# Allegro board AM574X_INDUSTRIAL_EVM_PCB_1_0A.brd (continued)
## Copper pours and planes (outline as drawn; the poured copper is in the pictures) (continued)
VDD_DSPEVE on L3_SIG1: 104.72,86.18 106.73,86.18 107.01,85.9 107.01,83.79 107.06,83.74 107.67,83.74 107.77,83.64 107.77,83.29 107.34,82.85 104.8,82.85 104.5,83.16 104.5,85.95
VDD_DSPEVE on L4_SIG2: 115.06,104.09 116.59,102.57 123.95,102.57 134.87,113.49 134.87,120.86 136.4,122.38 136.4,123.78 125.17,135.01 117.86,135.01 117.42,134.57 117.35,134.57 116.84,134.07 116.84,107.27 115.06,105.49
VDD_DSPEVE on L8_GND3: 112.39,106 111.63,105.24 111.63,93.43 107.19,88.98 107.19,87.84 105.92,86.57 105.28,86.57 104.77,86.06 104.77,83.39 105.03,83.14 107.44,83.14 107.7,83.39 107.7,83.77 109.09,85.17 121.03,85.17 123.95,88.09 123.95,105.49 123.44,106
VDD_DSPEVE on L10_SIG4: 113.54,87.08 114.43,87.08 115.19,86.31 115.19,84.92 115.06,84.79 113.54,84.79 113.03,85.3 113.03,86.57
VDD_DSPEVE on L10_SIG4: 115.34,103.69 115.06,103.97 115.06,104.98 115.95,105.87 117.98,105.87 118.69,105.16 118.69,104.12 118.26,103.69
VDD_DSPEVE on L10_SIG4: 115.19,98.13 115.19,98.89 115.57,99.27 117.37,99.27 117.47,99.17 117.47,98 117.07,97.59 115.72,97.59
VDD_DSPEVE on L10_SIG4: 104.65,86.14 106.86,86.14 106.98,86.01 106.98,83.49 106.5,83.01 105.03,83.01 104.42,83.62 104.42,85.91
VDD_GPU on TOP: 133.86,113.62 136.53,113.62 136.91,113.24 136.91,110.83 136.65,110.57 133.86,110.57 133.48,110.95 133.48,113.24
VDD_GPU on BOTTOM: 86.49,89.11 92.2,89.11 92.33,88.98 92.33,87.97 91.82,87.46 90.42,87.46 90.3,87.33 90.3,87.2 90.17,87.08 86.49,87.08 86.23,87.33 86.23,88.85
VDD_GPU on BOTTOM: 96.93,86.62 99.34,86.62 99.56,86.4 99.56,85.56 100.05,85.07 100.05,83.92 99.95,83.82 98.96,83.82 98.27,84.51 97.23,84.51 97.16,84.58 97.16,85.78 96.82,86.11 96.82,86.52
VDD_GPU on BOTTOM: 133.48,113.37 136.78,113.37 137.03,113.11 137.03,110.83 136.78,110.57 133.99,110.57 133.35,111.21 133.35,113.24
VDD_GPU on L3_SIG1: 97.69,86.21 98.73,86.21 100.03,84.91 100.03,83.97 99.9,83.85 98.65,83.85 98.4,83.59 98.4,83.36 99.21,82.55 99.21,82.17 99.11,82.07 97.94,82.07 97.54,82.47 97.54,86.06
VDD_GPU on L9_SIG3: 109.6,125.48 138.51,125.48 140.02,123.97 140.02,120.92 138.81,119.72 138.81,112.86 131.44,105.49 126.49,105.49 120.78,99.78 107.95,99.78 104.01,95.84 104.01,87.08 98.93,82 93.09,82 91.99,83.1 94.92,83.1 96.04,84.22 96.04,86.52 94.92,87.64 93.66,87.64 92.37,86.34 90.44,86.34 88.97,87.81 88.97,90.05 87.7,91.33 86.95,91.33 86.68,91.6 86.68,102.57 86.99,102.87
VDD_GPU on L10_SIG4: 86.23,88.85 86.36,88.98 92.2,88.98 92.46,88.73 92.46,87.84 91.95,87.33 90.04,87.33 89.79,87.08 86.36,87.08 86.23,87.2
VDD_GPU on L10_SIG4: 97.69,86.21 98.73,86.21 99.77,85.17 99.77,84.58 98.78,84.58 98.17,85.19 97.54,85.19 97.54,86.06
VDD_IVA on TOP: 143.26,113.62 146.05,113.62 146.43,113.24 146.43,110.95 146.18,110.7 143.38,110.7 143,111.08 143,113.37
VDD_IVA on BOTTOM: 89.89,78.08 90.17,78.36 92.84,78.36 93.22,77.98 98.34,77.98 99.11,78.74 99.82,78.74 100.03,78.54 100.03,77.07 99.69,76.74 93.47,76.74 91.28,74.55 90.04,74.55 89.89,74.7
VDD_IVA on L3_SIG1: 98.58,78.59 99.85,78.59 100.1,78.33 100.1,77.29 99.52,77.29 99.31,77.5 98.6,77.5 98.4,77.7 98.4,78.41
VDD_IVA on L9_SIG3: 98.78,76.33 98.3,76.81 98.3,80.77 98.71,81.18 99.11,81.18 104.77,86.84 104.77,95.2 108.97,99.4 120.9,99.4 126.62,105.11 131.95,105.11 139.52,112.68 139.52,119.79 140.21,120.48 140.21,122.64 140.61,123.04 146.94,123.04 147.57,122.41 147.57,111.51 140.42,104.35 140.42,103.8 117.42,80.8 108.46,80.8 103.99,76.33
VDD_IVA on L10_SIG4: 98.58,78.59 99.85,78.59 100.1,78.33 100.1,76.96 99.14,76.96 98.4,77.7 98.4,78.41
VDD_MIPI on TOP: 154.18,99.14 154.43,98.89 154.43,97.36 154.31,97.24 153.04,97.24 152.91,97.36 152.91,97.74 152.4,98.25 148.34,98.25 147.96,98.63 147.96,98.89 148.21,99.14
VDD_MPU on TOP: 108.84,133.81 109.35,134.32 112.27,134.32 112.27,131.02 114.81,128.48 118.75,128.48 119.76,127.46 119.76,122.51 118.87,121.62 114.55,121.62 108.84,127.34
VDD_MPU on TOP: 144.78,130.89 144.78,131.78 145.03,132.03 145.03,134.45 145.29,134.7 146.69,134.7 146.94,134.45 146.94,132.67 145.03,130.76 144.91,130.76
VDD_MPU on TOP: 102.95,79.83 104.06,79.83 104.34,80.11 105.82,80.11 106.5,79.43 106.5,77.42 105.23,77.42 104.44,78.21 102.95,78.21
VDD_MPU on BOTTOM: 101.17,79.71 101.42,79.96 102.49,79.96 102.97,79.48 102.97,79.05 102.77,78.85 101.5,78.85 101.17,79.18
VDD_MPU on BOTTOM: 105.97,80.17 106.96,80.17 107.19,79.94 107.19,79.58 106.91,79.3 106.88,79.3 106.88,78.47 108.89,78.47 109.14,78.21 109.14,76.74 108.99,76.59 108.1,76.59 107.72,76.97 106.86,76.97 106.81,76.92 106.76,76.92 106.07,77.6 104.42,77.6 104.29,77.73 104.29,80.7 104.7,81.11 105.66,81.11 105.79,80.98 105.79,80.35
VDD_MPU on BOTTOM: 95.63,95.97 99.31,95.97 99.57,95.71 99.57,94.49 99.31,94.23 95.59,94.23 95.38,94.44 95.38,95.71
VDD_MPU on BOTTOM: 115.64,80.42 117.15,80.42 117.3,80.27 117.3,78.94 117.09,78.74 115.91,78.74 115.44,79.2 115.44,80.22
VDD_MPU on L3_SIG1: 102.84,77.88 104.85,77.88 105.54,77.19 106.2,77.19 106.98,77.98 106.98,79.27 106.78,79.48 106.55,79.48 106.1,79.93 106.1,80.19 104.72,80.19 104.72,79.45 104.39,79.12 103.58,79.12 103.3,79.4 102.87,79.4 102.69,79.22 102.69,78.03
VDD_MPU on L6_PWR1: 95.63,118.19 106.81,129.37 106.81,129.24 107.7,130.13 116.97,130.13 126.87,140.04 144.91,140.04 147.19,137.75 147.19,131.91 146.56,131.27 144.65,131.27 143.13,132.8 141.22,132.8 140.59,132.16 138.68,132.16 137.67,133.18 133.48,133.18 128.02,127.72 128.02,116.03 121.67,109.68 121.67,105.36 119.63,103.33 119.63,77.68 119.04,77.09 100.79,77.09 100.61,77.27 100.61,81.76 101.42,82.58 101.42,88.4 95.63,94.19
VDD_MPU on L10_SIG4: 102.49,80.09 103.35,79.23 104.32,79.23 104.57,79.48 104.57,80.6 104.55,80.62 104.55,80.75 104.83,81.03 105.77,81.03 106.07,80.73 106.07,79.84 106.88,79.02 106.88,78.08 106.73,77.93 100.86,77.93 100.84,77.91 100.71,78.03 100.71,78.41 100.79,78.49 101.27,78.49 101.47,78.69 101.47,79.96 101.6,80.09
VDD_MPU on L10_SIG4: 95.89,94.06 95.89,95.59 96.52,96.22 97.41,96.22 97.79,95.84 97.79,93.43 97.54,93.17 96.77,93.17
VDD_RTC on TOP: 138.59,131.73 138.48,131.62 138.48,131.37 138.21,131.1 138.05,131.1 138.05,131.25 137.94,131.36 137.94,133.32 138.18,133.56 138.43,133.56 138.59,133.4
VDD_RTC on BOTTOM: 79.88,86.11 80.52,86.11 80.77,86.36 80.77,86.74 81.03,87 81.03,88.01 80.9,88.14 80.26,88.14 79.76,87.63 79.76,86.23
VDD_RTC on L9_SIG3: 105.11,134.19 138.3,134.19 139.32,133.18 139.32,127.21 138.35,126.24 109.09,126.24 85.85,103 85.85,91.49 85.22,90.85 85.22,89.92 81.79,86.49 81.79,85.09 81.53,84.84 80.26,84.84 78.11,87 78.11,107.19
VDD_RTC on L10_SIG4: 80.26,88.01 81.03,88.01 81.28,87.76 81.28,87.38 81.03,87.12 81.03,86.23 80.64,85.85 79.88,85.85 79.5,86.23 79.5,87.25
VDDR2_VREF on BOTTOM: 139.7,70.82 141.22,70.82 141.48,70.57 141.48,67.14 140.59,66.25 140.21,66.25 139.45,67.01 139.45,70.57
VDDR2_VREF on BOTTOM: 139.7,55.58 141.22,55.58 141.48,55.33 141.48,51.9 140.59,51.01 140.21,51.01 139.45,51.77 139.45,55.33
VDDR2_VREF on BOTTOM: 162.08,59.87 162.08,58.32 160.96,58.32 160.96,59.21 159,61.17 159,63.07 155.19,66.88 155.19,70.19 151.38,74 141.86,74 140.34,72.47 138.56,72.47 138.18,72.85 138.18,74.63 139.57,76.03 152.65,76.03 157.35,71.33 157.35,67.67 161.42,63.61 161.42,60.53
VDDR2_VREF on L7_PWR2: 141.35,45.42 138.68,48.09 138.68,56.98 137.67,57.99 117.98,57.99 108.84,67.14 108.84,70.19 107.06,71.96 104.77,71.96 103.63,73.11 103.63,74.76 104.01,75.14 109.35,75.14 111.63,72.85 111.63,68.33 117.73,62.23 129.71,62.23 133.73,66.25 133.73,71.58 136.95,74.8 140.04,74.8 143.89,70.95 143.89,62.86 144.4,62.36 144.4,60.83 143.89,60.32 143.89,46.06 143.26,45.42
VDDR2_VTT on TOP: 142.75,71.07 150.41,71.07 151.13,70.36 151.13,56.98 151.38,56.72 152.15,56.72 152.91,57.49 158.12,57.49 158.24,57.61 158.24,58.88 158.12,59.01 153.54,59.01 152.91,59.64 152.91,70.99 151.05,72.85 142.75,72.85 142.49,72.6 142.49,71.33
VDDR2_VTT on BOTTOM: 151.13,70.31 150.37,71.07 141.86,71.07 141.61,71.33 141.61,72.6 141.86,72.85 151,72.85 152.91,70.95 152.91,60.66 154.46,59.11 156.01,59.11 156.21,58.91 156.21,58.42 156.44,58.2 157,58.2 157.15,58.04 157.15,57.84 157.05,57.74 157.05,57.66 156.97,57.59 156.97,57.49 151.38,57.49 151.13,57.74
VDDR_VREF on TOP: 78.61,33.78 81.03,33.78 82.04,32.77 82.93,32.77 83.06,32.89 83.31,32.89 83.44,32.77 83.44,32.51 82.8,31.88 78.49,31.88 78.11,32.26 78.11,33.27
VDDR_VREF on TOP: 93.85,33.78 96.27,33.78 97.28,32.77 98.17,32.77 98.3,32.89 98.55,32.89 98.68,32.77 98.68,32.51 98.04,31.88 93.73,31.88 93.34,32.26 93.34,33.27
VDDR_VREF on TOP: 105.44,12.55 106.98,12.55 106.98,13.67 106.1,13.67 104.14,15.62 98.76,15.62 92.79,21.59 91.19,21.59 90.68,21.08 90.68,20.19 97.66,13.21 104.77,13.21
VDDR_VREF on TOP: 109.09,33.78 111.51,33.78 112.52,32.77 113.41,32.77 113.54,32.89 113.79,32.89 113.92,32.77 113.92,32.51 113.28,31.88 108.97,31.88 108.58,32.26 108.58,33.27
VDDR_VREF on L7_PWR2: 92.46,18.83 90.55,20.74 90.55,26.88 88.65,28.78 83.44,28.78 82.55,29.67 82.55,33.61 83.19,34.24 86.23,34.24 95.76,43.77 95.76,65.16 96.52,65.92 96.52,78.19 96.77,78.44 99.82,78.44 100.03,78.24 100.03,77.42 102.74,74.71 102.74,38.94 103.25,38.44 120.27,38.44 123.19,35.51 123.19,27.72 122.3,26.83 97.54,26.83 96.01,25.31 96.01,19.85 95,18.83
VDDR_VTT on TOP: 107.31,17.27 107.06,17.53 107.06,17.78 106.3,18.54 106.3,27.81 106.55,28.07 108.46,28.07 108.71,27.81 108.71,25.4 109.6,24.51 110.62,24.51 111.89,23.24 111.89,22.61 112.9,21.59 120.78,21.59 121.5,20.87 124.5,20.87 125.13,21.5 125.13,24.98 124.21,25.91 124.21,27.81 124.46,28.07 125.86,28.07 126.36,28.58 126.36,30.48 125.86,30.99 124.84,30.99 124.21,31.62 124.21,32.13 124.46,32.38 127.38,32.38 129.03,30.73 129.03,26.16 128.14,25.27 128.14,20.07 126.11,18.03 118.39,18.03 115.85,20.57 111.51,20.57 109.98,22.1 108.33,22.1 107.82,21.59 107.82,17.53 107.57,17.27
VDDR_VTT on BOTTOM: 107.31,23.62 108.46,22.48 110.62,22.48 111.38,21.72 111.38,19.3 111.76,18.92 127.13,18.92 128.35,20.14 128.35,29.69 128.07,29.97 124.41,29.97 124.21,29.77 124.21,22.48 123.32,21.59 114.05,21.59 113.54,22.1 113.54,22.61 108.71,27.43 108.71,28.19 108.58,28.32 108.58,30.61 108.46,30.73 107.57,30.73 107.31,30.48
VDDS_DDR on TOP: 108.71,17.06 109.09,17.44 109.09,17.95 109.73,18.59 109.73,20.11 109.98,20.37 109.98,21.46 109.73,21.72 108.46,21.72 108.2,21.46 108.2,17.06
VDDS_DDR on TOP: 141.48,53.04 141.86,53.04 142.11,52.79 142.11,51.52 142.37,51.26 142.37,50.37 141.86,49.87 141.61,49.87 141.35,50.12 141.35,51.14 141.22,51.26 141.22,52.79
VDDS_DDR on TOP: 61.09,75.01 64.01,75.01 64.14,74.88 64.14,72.6 63.63,72.09 60.96,72.09 60.58,72.47 60.58,74.5
VDDS_DDR on TOP: 65.15,56.98 65.15,54.06 65.02,53.93 62.74,53.93 62.23,54.44 62.23,57.1 62.61,57.49 64.64,57.49
VDDS_DDR on TOP: 156.08,57.1 156.21,56.98 156.21,55.71 156.08,55.58 153.16,55.58 152.91,55.83 152.91,56.85 153.16,57.1
VDDS_DDR on TOP: 136.14,63.33 136.65,63.33 137.41,64.09 137.41,65.49 137.16,65.74 136.65,65.74 135.89,64.98 135.89,63.58
VDDS_DDR on TOP: 151.64,116.67 148.46,116.67 148.21,116.92 148.21,118.32 145.61,120.92 145.61,122.19 144.91,122.89 144.91,123.02 145.16,123.27 145.54,123.27 145.8,123.02 146.94,123.02 148.72,121.24 150.5,121.24 150.88,120.86 150.88,119.46 151.89,118.45 151.89,116.92
VDDS_DDR on TOP: 135,48.21 136.4,48.21 136.65,48.47 136.65,49.48 137.16,49.99 137.16,50.25 136.78,50.63 135,50.63 134.75,50.37 134.75,48.47
VDDS_DDR on TOP: 139.19,50.37 140.21,50.37 140.56,50.02 140.56,48.57 140.08,48.09 139.19,48.09 138.94,48.34 138.94,50.12
VDDS_DDR on BOTTOM: 86.74,33.43 87.1,33.78 87.38,33.78 87.63,33.53 87.63,32.26 87.25,31.88 84.33,31.88 83.69,32.51 83.69,33.3 83.82,33.43
VDDS_DDR on BOTTOM: 83.95,36.32 85.85,36.32 86.11,36.07 86.11,35.69 85.85,35.43 83.95,35.43 83.69,35.69 83.69,36.07
VDDS_DDR on BOTTOM: 157.56,56.6 157.18,56.22 156.67,56.22 156.04,55.58 153.33,55.58 153.1,55.81 153.1,56.91 153.29,57.1 157.56,57.1
VDDS_DDR on BOTTOM: 109.86,18.54 110.11,18.8 110.11,21.46 109.73,21.84 108.58,21.84 108.2,21.46 108.2,18.67 108.33,18.54
VDDS_DDR on L6_PWR1: 151.26,119.21 144.4,119.21 141.99,116.79 133.22,116.79 132.33,115.91 132.33,114.76 126.24,108.67 126.24,105.49 125.09,104.35 121.41,104.35 120.27,103.21 120.27,77.35 119.93,77 119.93,48.63 113.66,42.37 67.18,42.37 65.15,44.4 65.15,73.84 63.91,75.09 51,75.09 49.78,73.87 49.78,26.37 51.64,24.52 65.46,24.52 71.58,18.39 82.55,18.39 84.86,16.08 97.66,16.08 99.95,18.37 111.76,18.37 112.78,17.35 113.41,17.35 114.43,18.37 164.21,18.37 168.4,22.56 168.4,66.25 163.96,70.69 156.34,70.69 152.65,74.38 152.65,87.39 152.02,88.03 143.07,88.03 140.59,90.51 140.59,101.94 152.02,113.37 152.02,118.45
AM572X_USB1_DRVVBUS on L9_SIG3: 93.7,87.33 94.74,87.33 95.76,86.31 95.76,84.27 94.82,83.33 91.56,83.33 86.5,88.39 86.5,88.4 85.72,89.18 85.72,90.63 85.98,90.89 87.46,90.89 88.55,89.8 88.55,87.97 90.48,86.03 92.41,86.03 92.41,86.04
BKLT_L on TOP: 70.86,144.25 70.36,144.75 70.36,146.41 70.74,146.79 80.13,146.79 80.64,146.28 80.64,144.63 80.26,144.25
BKLT_L on BOTTOM: 73.13,146.61 73.13,145.6 72.24,145.6 71.48,144.84 70.59,144.84 70.36,145.07 70.36,146.38 70.59,146.61
BKLT_SW on TOP: 70.74,140.94 70.36,141.33 70.36,143.48 70.74,143.87 80.26,143.87 80.64,143.48 80.64,141.58 80.01,140.94
BKLT_SW on BOTTOM: 73.15,143.57 73.15,142.7 72.27,142.7 71.86,142.3 70.34,142.3 70.09,142.55 70.09,143.31 70.34,143.57
ETH1_LDO_O on TOP: 64.64,111.08 65.53,111.08 65.79,110.83 65.79,107.78 65.66,107.65 64.52,107.65 64.39,107.78 64.39,110.83
FTDI_VPHY on BOTTOM: 158.8,83.13 164.01,83.13 164.39,82.75 164.39,81.48 164.13,81.22 159.18,81.22 158.55,81.86 158.55,82.87
FTDI_VPLL on BOTTOM: 158.93,81.16 164.13,81.16 164.52,80.78 164.52,79.51 164.21,79.2 159.36,79.2 158.67,79.89 158.67,80.9
VADD33_PRU1ETH0 on BOTTOM: 21.97,121.87 21.97,123.14 22.48,123.65 23.37,123.65 23.62,123.4 23.62,123.02 23.37,122.76 23.11,122.76 22.23,121.87
VADD33_PRU1ETH1 on TOP: 26.11,100.54 26.54,100.54 27.03,100.06 27.03,98.63 26.8,98.4 26.39,98.4 26.16,98.63 26.16,99.78 25.88,100.06 25.88,100.31
VADD33_PRU1ETH1 on BOTTOM: 26.37,101.43 29.79,101.43 29.92,101.3 29.92,100.16 29.67,99.9 27.53,99.9 27.03,99.4 27.03,98.63 26.77,98.38 26.37,98.38 25.98,98.76 25.98,101.05
VADD33_PRU2ETH0 on TOP: 26.06,82.78 26.54,82.78 26.97,82.35 26.97,80.9 26.8,80.73 26.31,80.73 25.98,81.06 25.98,82.4 26.06,82.48
VADD33_PRU2ETH0 on BOTTOM: 26.37,83.73 29.79,83.73 29.92,83.6 29.92,82.46 29.67,82.2 29.03,82.2 27.51,80.68 26.37,80.68 25.98,81.06 25.98,83.35
VADD33_PRU2ETH1 on TOP: 26.37,57.41 27.51,57.41 27.74,57.18 27.74,56.8 27.53,56.6 27.1,56.6 26.97,56.47 26.97,56.11 26.72,55.86 26.31,55.86 26.16,56.01 26.16,57.18 26.37,57.38
VADD33_PRU2ETH1 on BOTTOM: 26.37,58.96 29.79,58.96 29.92,58.84 29.92,57.69 29.67,57.44 29.03,57.44 29,57.41 28.4,57.41 27.56,56.57 27.3,56.57 27,56.27 27,55.91 26.37,55.91 25.98,56.3 25.98,58.58
VAM572X_DDR1 on TOP: 61.09,78.69 63.63,78.69 64.14,78.19 64.14,75.9 64.01,75.77 61.09,75.77 60.71,76.15 60.71,78.31
VAM572X_DDR1 on TOP: 67.06,72.47 69.22,72.47 69.72,71.96 69.72,71.2 69.22,70.69 67.06,70.69 66.55,71.2 66.55,71.96
VAM572X_DDR1 on TOP: 95.94,76.71 97.18,76.71 97.33,76.56 97.33,75.26 97.08,75.01 95,75.01 94.82,75.18 94.82,75.59
VAM572X_DDR1 on BOTTOM: 66.29,72.47 71.37,72.47 72.01,71.84 72.01,66.88 71.5,66.38 67.18,66.38 65.79,67.77 65.79,71.96
VAM572X_DDR1 on BOTTOM: 93.88,75.98 95.17,75.98 95.76,75.39 95.97,75.39 95.97,73.28 97.73,71.52 97.73,71.29 97.49,71.05 97.49,70.79 97.33,70.64 95.96,70.64 95.76,70.84 95.76,71.65 95.63,71.78 94.51,71.78 94.39,71.65 94.39,70.28 94.26,70.15 92.71,70.15 92.64,70.22 92.64,71.7 93.7,72.76 93.7,75.8
VAM572X_DDR1 on L3_SIG1: 95.38,76.28 96.65,76.28 96.85,76.07 96.85,75.23 96.6,74.98 94.54,74.98 94.54,75.44
VAM572X_DDR1 on L6_PWR1: 98.04,68.15 95.63,65.74 65.91,65.74 65.79,65.87 65.79,74.12 64.14,75.77 60.2,75.77 59.44,76.54 59.44,82.17 60.91,83.65 94.23,83.65 94.46,83.42 100.78,83.42 100.78,83.42 100.78,79.4 100.18,78.8 100.18,76.66 98.04,74.53
VAM572X_DDR1 on L10_SIG4: 96.52,71.46 96.14,71.07 95.76,71.07 95.63,71.2 95.63,71.46 95.18,71.91 94.82,71.91 94.13,71.22 93.75,71.22 93.55,71.42 93.55,72.26 93.57,72.26 94.61,73.3 94.61,73.89 93.8,74.7 93.8,75.18 94.01,75.39 94.56,75.39 95.3,76.12 96.19,76.12 96.19,74.4 96.52,74.07
VAM572X_DDR2 on TOP: 68.83,56.98 68.83,54.44 68.33,53.93 66.04,53.93 65.91,54.06 65.91,56.98 66.29,57.36 68.45,57.36
VAM572X_DDR2 on TOP: 103.86,77.44 103.86,75.82 105.54,75.82 105.61,75.9 105.61,76.99 105.54,77.06 105.33,77.06 105.18,76.91 104.9,76.91 104.37,77.44
VAM572X_DDR2 on BOTTOM: 114.3,54.69 121.03,54.69 121.92,55.58 121.92,58.12 120.9,59.14 114.68,59.14 113.66,58.12 113.66,55.33
VAM572X_DDR2 on BOTTOM: 110.06,71.05 110.06,72.75 110.67,73.36 110.67,74.93 110.54,75.06 109.25,75.06 108.89,75.41 108.89,75.8 108.69,76 108.41,76 107.95,76.46 104.39,76.46 104.39,75.39 104.52,75.27 105.16,75.27 105.28,75.14 105.28,75.11 105.66,75.11 106.1,74.68 106.1,72.85 105.77,72.52 105.11,72.52 104.8,72.83 103.88,72.83 103.7,72.65 101.32,72.65 100.81,73.16 100.49,73.16 100.43,73.11 100.43,72.16 100.58,72.01 100.91,72.01 101,72.09 104.17,72.09 104.68,71.58 105.31,71.58 106.68,70.21 109.22,70.21
VAM572X_DDR2 on L3_SIG1: 100.41,73.84 101.09,73.84 101.45,73.48 101.45,72.47 101.12,72.14 100.46,72.14 100.18,72.42 100.18,73.61
VAM572X_DDR2 on L3_SIG1: 107.67,76.91 108.41,76.91 108.71,76.61 108.71,75.69 109.47,74.93 109.47,73.79 108.2,73.79 107.59,74.4 107.59,76.83
VAM572X_DDR2 on L3_SIG1, L10_SIG4: 104.42,77.01 105.49,77.01 105.64,76.86 105.89,76.86 106.22,76.53 106.22,75.49 105.89,75.16 104.57,75.16 104.37,75.36 104.37,76.96
VAM572X_DDR2 on L6_PWR1: 119.3,76.21 119.3,48.92 113.39,43 67.44,43 65.79,44.66 65.79,64.85 66.04,65.11 96.01,65.11 98.55,67.65 98.55,74.5 100.85,76.8 118.72,76.8
VAM572X_DDR2 on L10_SIG4: 113.66,56.85 120.9,56.85 121.54,56.22 121.54,54.82 121.03,54.31 113.66,54.31 113.03,54.95 113.03,56.22
VAM572X_DDR2 on L10_SIG4: 107.67,76.91 108.41,76.91 108.71,76.61 108.71,75.69 110.92,73.48 110.92,72.97 110.64,72.69 109.3,72.69 107.59,74.4 107.59,76.83
VCAN1 on TOP: 165.96,29.6 167.94,29.6 168.33,29.21 168.33,26.04 165.56,23.27 157.53,23.27 155.63,21.37 155.63,13.92 154.53,12.83 151.54,12.83 151,13.37 148.54,13.37 148.08,13.82 148.08,19.89 155.07,26.88 164.54,26.88 165.35,27.69 165.35,28.99
VETH0_AVDDH on BOTTOM: 48.13,116.92 48.89,116.16 48.89,113.75 48.51,113.37 47.5,113.37 46.86,114 46.86,117.94 46.48,118.32 46.48,123.91 46.74,124.16 47.88,124.16 48.13,123.91
VETH0_AVDDH on L4_SIG2: 30.48,127.34 44.96,127.34 47.75,124.54 47.75,122.51 46.61,121.37 40.26,121.37 37.08,124.54 30.61,124.54 29.97,125.18 29.97,126.83
VETH0_AVDDL on BOTTOM: 43.69,123.65 43.69,124.8 43.43,125.05 38.84,125.05 38.33,125.56 33.66,125.56 33.15,125.05 33.15,124.41 33.66,123.91 37.87,123.91 38.25,123.53 43.56,123.53
VETH0_AVDDL_PLL on BOTTOM: 38.94,123.02 43.05,123.02 43.81,122.26 43.81,121.24 43.56,120.99 38.99,120.99 38.73,121.24 38.73,122.81
VETH0_AVDDL_PMOS on BOTTOM: 43.31,109.17 43.31,110.32 44.7,111.71 44.7,117.56 44.2,118.06 44.2,125.05 43.81,125.43 43.81,126.95 44.32,127.46 46.1,127.46 46.48,127.08 46.48,125.56 45.97,125.05 45.97,118.06 46.61,117.43 46.61,112.22 47.62,111.21 47.62,109.05 47.24,108.67 43.81,108.67
VETH0_DVDDH on BOTTOM: 28.45,118.19 29.08,118.19 30.23,117.05 30.43,117.05 30.86,116.62 30.86,116.16 30.35,115.65 28.45,115.65 27.69,116.41 27.69,117.43
VETH0_DVDDH on L4_SIG2: 29.34,122.89 29.97,122.89 32.38,120.48 42.42,120.48 43.18,119.72 43.18,111.33 43.14,111.29 43.14,108.6 42.07,107.52 38.32,107.52 38.14,107.7 38.14,109.66 39.88,111.4 39.88,112.86 39.24,113.49 30.86,113.49 28.45,115.91 27.43,115.91 27.05,116.29 27.05,120.6
VETH0_DVDDL on BOTTOM: 43.56,119.59 43.81,119.33 43.81,118.45 43.56,118.19 42.55,118.19 41.27,116.92 38.61,116.92 37.41,115.73 32.21,115.73 29.59,118.34 29.59,122.51 30.48,123.4 31.62,123.4 32.77,122.26 32.77,121.49 34.67,119.59
VETH1_AVDDH on TOP: 72.9,106.25 72.39,105.75 69.34,105.75 68.96,106.13 68.96,110.19 70.61,111.84 70.61,116.67 69.47,117.81 69.47,127.59 68.58,128.48 64.64,128.48 64.01,129.11 64.01,130.51 64.26,130.76 70.48,130.76 72.9,128.35
VETH1_AVDDH on BOTTOM: 50.67,127.08 52.45,127.08 53.09,126.45 58.06,126.45 62.38,130.76 66.67,130.76 67.06,130.38 67.06,128.86 66.67,128.48 62.03,128.48 60.2,126.65 60.2,125.53 60.1,125.43 59.21,125.43 59.08,125.56 54.81,125.56 53.8,124.54 50.67,124.54 50.29,124.92 50.29,126.7
VETH1_AVDDL on TOP: 65.53,123.27 65.28,123.02 64.14,123.02 63.63,123.53 63.63,124.8 63.88,125.05 65.41,125.05 65.53,124.92
VETH1_AVDDL on BOTTOM: 65.66,124.54 65.15,125.05 59.05,125.05 58.55,125.56 55.37,125.56 54.86,125.05 54.86,124.41 55.68,123.6 64.31,123.6 64.9,123.02 65.41,123.02 65.66,123.27
VETH1_AVDDL_PLL on TOP: 64.39,122.64 65.28,122.64 65.53,122.38 65.53,120.86 65.28,120.6 64.14,120.6 63.88,120.86 63.88,121.24 64.14,121.49 64.14,122.38
VETH1_AVDDL_PLL on BOTTOM: 60.71,123.27 64.52,123.27 65.53,122.26 65.53,120.99 65.28,120.73 64.01,120.73 63.75,120.99 60.58,120.99 60.32,121.24 60.32,122.89
VETH1_AVDDL_PMOS on TOP: 65.91,111.46 65.91,128.22 66.42,128.73 67.69,128.73 68.77,127.65 68.77,116.98 69.47,116.29 69.47,112.6 68.2,111.33 68.2,107.78 67.82,107.4 66.8,107.4 66.55,107.65 66.55,110.83
VETH1_DVDDH on BOTTOM: 50.04,115.02 51.31,115.02 51.43,114.89 51.43,112.6 51.31,112.48 49.4,112.48 49.15,112.73 49.15,114.51 49.53,114.89 49.91,114.89
VETH1_DVDDH on L4_SIG2: 52.07,122.89 61.59,122.89 64.26,120.22 64.26,111.08 61.93,108.74 49.76,108.74 48.64,109.86 48.64,119.59 47.88,120.35 47.88,121.62 49.78,123.53 51.43,123.53
VETH1_DVDDL on BOTTOM: 58.55,118.19 59.44,118.19 60.83,119.59 64.01,119.59 64.01,119.84 64.52,120.35 65.28,120.35 65.53,120.1 65.53,117.81 64.64,116.92 60.32,116.92 58.93,115.52 51.43,115.52 51.31,115.65 51.31,122.51 52.2,123.4 53.34,123.4 54.48,122.26 54.48,119.97 55.5,118.95 57.78,118.95
VLDO2_OUT on TOP: 138.83,133.32 138.94,133.43 138.94,133.81 139.07,133.94 139.32,133.94 139.47,133.78 139.47,131.27 139.32,131.12 139.32,130.31 139.24,130.23 139.04,130.23 138.83,130.44
VLDO2_OUT on BOTTOM: 138.94,133.18 138.94,131.65 139.07,131.53 139.95,131.53 140.21,131.78 140.21,133.86 139.49,134.57 138.56,134.57 138.3,134.32 138.3,133.81
VLED+ on BOTTOM: 73.41,136.86 70.36,136.86 69.98,137.24 69.98,138.64 70.23,138.89 70.23,141.69 70.48,141.94 72.36,141.94 73.28,142.32 73.41,142.45 73.66,142.45 73.79,142.32 73.79,137.24
VLED+ on L9_SIG3: 71.25,141.81 72.39,141.81 82.55,131.65 82.55,128.48 81.91,127.84 80.01,127.84 70.61,137.24 70.61,141.18
VLED- on BOTTOM: 82.42,124.8 81.79,125.43 81.79,127.08 82.04,127.34 82.68,127.34 82.8,127.46 84.96,127.46 85.09,127.34 85.09,125.05 84.84,124.8
VLED- on BOTTOM: 76.07,146.64 76.58,147.15 81.41,147.15 82.04,146.51 82.04,145.12 81.61,144.68 78.18,144.68 77.5,145.37 75.79,145.37 75.54,145.62 75.06,145.62 74.93,145.75 74.93,146.51 75.06,146.64
VLED- on L9_SIG3: 77.85,146.51 78.87,147.53 81.03,147.53 88.77,139.78 88.77,126.45 86.36,124.03 81.91,124.03 81.28,124.67 81.28,126.7 81.66,127.08 81.91,127.08 84.96,130.13 84.96,131.02 84.9,131.08 84.9,136.54 77.85,143.59
VMAIN on TOP: 75.69,130.76 74.3,129.37 74.3,115.52 76.71,113.11 76.71,110.32 75.82,109.43 75.82,107.9 76.33,107.4 79.5,107.4 81.91,109.81 81.91,113.87 79.25,116.54 79.25,128.35 79.63,128.73 79.63,130.26 79.12,130.76
VMAIN on TOP: 185.7,119.97 176.29,119.97 172.36,116.04 172.36,112.35 166.65,106.63 166.65,102.72 166.12,102.19 162.59,102.19 162.08,102.7 162.08,111.08 166.01,115.02 168.68,115.02 169.95,116.29 169.95,125.68 170.21,125.94 177.7,125.94 178.21,126.45 185.8,126.45 186.94,125.3 186.94,121.21
VMAIN on TOP: 140.21,120.73 141.22,120.73 141.54,120.41 141.54,118.89 141.48,118.83 140.59,118.83 140.02,119.4 140.02,120.54
VMAIN on TOP: 137.29,121.24 137.29,120.1 136.65,119.46 135.26,119.46 135.13,119.59 135.13,119.97 136.02,120.86 136.02,121.11 136.27,121.37 137.16,121.37
VMAIN on TOP: 158.12,123.91 158.75,123.91 159,124.16 159,128.48 158.37,129.11 158.37,133.94 158.24,134.07 156.08,134.07 155.32,133.3 155.32,128.86 156.08,128.1 157.48,128.1 157.86,127.72 157.86,124.16
VMAIN on BOTTOM: 133.41,127.85 133.41,130.54 132.9,131.05 131.57,131.05 131.42,131.2 131.42,132.78 131.68,133.04 135.01,133.04 136.08,131.97 136.08,130.78 135.13,129.83 135.13,128.86 135.64,128.35 135.76,128.35 136.14,127.97 136.14,126.83 135.64,126.32 134.87,126.32 134.11,125.56 133.1,125.56 132.97,125.68 132.97,127.41
VMAIN on BOTTOM: 137.03,121.62 137.03,120.1 136.78,119.84 136.78,117.94 137.03,117.68 142.49,117.68 143,118.19 143,121.24 142.88,121.37 138.68,121.37 138.18,121.87 137.29,121.87
VMAIN on BOTTOM: 145.36,132.11 144.68,131.42 141.27,131.42 141.1,131.6 141.1,132.16 141.73,132.8 141.73,133.86 142.06,134.19 145.29,134.19 145.36,134.12
VMAIN on BOTTOM: 145.01,129.65 146.63,129.65 147.07,129.21 147.07,128.27 146.79,128 145.39,128 144.88,128.5 144.88,129.52
VMAIN on BOTTOM: 70.74,111.21 72.26,111.21 72.52,110.95 72.52,109.17 79.12,109.17 79.38,108.92 79.38,108.16 78.49,107.27 70.87,107.27 70.74,107.4
VMAIN on BOTTOM: 155.83,129.88 158.5,129.88 159.64,128.73 159.64,126.07 159.39,125.81 158.37,125.81 158.12,126.07 158.12,127.59 157.73,127.97 156.21,127.97 155.58,128.61 155.58,129.62
VMAIN on BOTTOM: 146.77,125.81 148.84,125.81 149.1,125.56 149.1,122.89 147.7,121.49 147.7,119.84 147.57,119.72 145.03,119.72 144.65,120.1 144.65,121.92 145.03,122.3 145.03,124.59 145.54,124.59
VMAIN on BOTTOM: 154.74,106.9 154.23,106.9 153.32,107.81 151.48,107.81 151,108.29 149.48,108.29 149.23,108.03 149.23,106.51 149.47,106.27 154.74,106.27
VMAIN on BOTTOM: 166.14,112.98 169.32,112.98 171.09,114.76 171.09,118.83 173.38,121.11 186.31,121.11 186.94,121.75 186.94,125.81 186.44,126.32 167.28,126.32 166.65,125.68 166.65,120.48 165.56,119.38 165.56,113.57
VMAIN on BOTTOM: 73.51,145.72 73.51,146.87 73.13,147.25 72.75,147.25 72.63,147.38 72.63,148.52 72.5,148.65 72.5,148.67 72.37,148.8 70.99,148.8 70.1,149.69 70.1,150.58 70.42,150.89 73.98,150.89 74.28,150.59 74.28,149.28 74.02,149.03 74.02,147.25 73.77,146.99 73.77,145.72
VMAIN on L3_SIG1: 142.88,128.99 145.16,128.99 145.8,129.62 146.81,129.62 147.07,129.37 147.07,128.35 146.94,128.22 143,128.22 142.75,128.48 142.75,128.86
VMAIN on L3_SIG1: 136.27,129.15 136.49,128.94 137.68,128.94 137.8,129.06 137.8,129.53 137.99,129.72 138.58,129.72 138.73,129.57 138.73,129.26 138.84,129.14 140.05,129.14 140.26,129.36 140.26,130.48 140.79,131 142.14,131 142.39,131.26 142.39,132.13 142.09,132.43 140.18,132.43 139.65,131.9 139.65,130.96 139.46,130.76 139.18,130.76 138.86,131.09 137.09,131.09 136.53,131.65 136.53,132.03 135.64,132.92 133.73,132.92 133.6,132.8 133.6,131.91 134.37,131.15 135.76,131.15 136.27,130.64
VMAIN on L3_SIG1: 142.68,125.74 142.68,124.83 142.96,124.54 145.03,124.54 145.31,124.82 147.47,124.82 147.7,125.05 147.7,126.07 147.45,126.32 145.16,126.32 144.78,125.94 142.88,125.94
VMAIN on L3_SIG1: 144.53,122.76 147.7,122.76 148.08,122.38 148.08,122 147.32,121.24 145.03,121.24 144.27,122 144.27,122.51
VMAIN on L3_SIG1: 135,119.08 135,119.97 136.4,121.37 141.1,121.37 141.86,120.6 141.86,118.7 141.73,118.57 135.51,118.57
VMAIN on L3_SIG1: 132.72,124.92 135.64,124.92 136.14,124.41 136.14,123.78 132.59,123.78 132.46,123.91 132.46,124.67
VMAIN on L6_PWR1: 168.66,132.42 168.78,132.54 168.78,92.56 166.32,92.56 166.32,92.51 162.66,88.85 143.12,88.85 141.22,90.75 141.22,101.3 152.53,112.6 152.53,118.83 151.51,119.84 144.15,119.84 141.73,117.43 133.48,117.43 132.33,118.57 132.33,126.57 134.87,129.11 136.53,129.11 138.43,131.02 138.81,131.02 139.45,131.65 140.59,131.65 141.22,132.29 142.88,132.29 144.4,130.76 146.43,130.76 147.57,131.91 147.57,137.88 145.03,140.42 126.36,140.42 116.84,130.89 116.84,130.76 84.71,130.76 84.71,130.51 82.68,128.48 82.68,126.57 82.42,126.32 73.79,126.32 70.48,129.62 70.48,134.7 70.61,134.83 70.61,149.8 71.31,150.5 83.75,150.5 84.35,149.9 96.53,149.9 97.13,150.5 168.42,150.5 168.66,150.26
VMAIN on L10_SIG4: 133.73,128.48 135.89,128.48 136.27,128.1 136.27,127.08 134.11,124.92 134.11,124.03 133.86,123.78 132.59,123.78 132.33,124.03 132.33,127.08
VMAIN on L10_SIG4: 144.65,129.62 144.78,129.75 147.19,129.75 147.32,129.62 147.32,128.61 147.07,128.35 144.91,128.35 144.65,128.61
VMAIN on L10_SIG4: 145.11,126.06 147.75,126.06 148.08,125.73 148.08,121.49 147.7,121.11 145.16,121.11 144.65,121.62 144.65,122.26 144.91,122.51 144.91,125.86
VMAIN on L10_SIG4: 132.74,132.57 133.1,132.92 135.71,132.92 136.14,132.49 136.14,130.66 135.83,130.35 133.09,130.35 132.74,130.7
VMAIN on L10_SIG4: 136.27,121.49 140.72,121.49 141.61,120.6 141.61,118.83 141.48,118.7 136.02,118.7 135.64,119.08 135.64,120.86
VMAIN on L10_SIG4: 138.68,130.76 138.81,130.76 139.95,131.91 139.95,132.67 140.46,133.18 143.38,133.18 143.64,132.92 143.64,131.65 143,131.02 140.72,131.02 139.57,129.88 138.81,129.88 138.56,130.13 138.56,130.64
VPROFI on TOP: 114.55,4.32 114.94,3.94 115.95,3.94 116.2,4.19 118.75,4.19 119,3.94 119,2.41 118.75,2.16 112.14,2.16 111.89,2.41 111.89,3.94 112.27,4.32
VPROFI on BOTTOM: 99.44,10.24 103.17,10.24 103.63,9.78 103.63,8.13 103.25,7.75 103.25,6.22 102.87,5.84 99.27,5.84 98.81,6.3 98.81,9.61
VPROFI on L3_SIG1: 98.68,6.83 99.52,7.67 108.92,7.67 112.37,4.22 114,4.22 114.45,3.76 114.45,1.88 113.84,1.27 110.34,1.27 109.52,2.08 109.52,2.97 107.49,5 105.23,5 104.8,4.57 99.06,4.57 98.68,4.95
VPROFI_SRC on BOTTOM: 99.44,12.7 108.46,12.7 113.41,7.75 117.22,7.75 117.47,8 117.47,9.53 117.98,10.03 119.13,10.03 119.38,9.78 119.38,6.48 119.13,6.22 117.47,6.22 116.33,5.08 111.38,5.08 105.66,10.79 99.31,10.79 99.19,10.92 99.19,12.45
VPROFI_TRANSA on BOTTOM: 117.35,13.46 121.54,13.46 123.06,11.94 123.06,10.54 122.94,10.41 121.54,10.41 119.76,12.19 117.22,12.19 117.09,12.32 117.09,13.21
VPROFI_TRANSB on BOTTOM: 117.86,4.06 120.14,4.06 121.28,5.21 121.28,5.84 121.54,6.1 123.32,6.1 123.57,5.84 123.57,3.94 121.92,2.29 117.86,2.29 117.47,2.67 117.47,3.68
VPWRIN_JCK on TOP: 176.94,102.76 176.68,103.01 176.68,105.87 172.84,109.72 172.84,113.8 173.89,114.86 176.85,114.86 178.97,112.74 178.97,110.19 180.62,108.54 183.16,108.54 184.81,110.19 184.81,111.33 185.57,112.1 187.99,112.1 188.75,111.33 188.75,104.48 187.03,102.76 ; 1 cut-out
VPWRIN_JCK on BOTTOM: 171.48,109.68 164.36,109.68 163.86,110.19 163.86,112.1 164.24,112.48 170.59,112.48 173.51,115.4 177.19,115.4 178.97,113.62 178.97,110.19 180.62,108.54 183.16,108.54 184.81,110.19 184.81,111.71 185.57,112.48 188.11,112.48 188.62,111.97 188.62,104.35 187.03,102.76 178.4,102.76
VPWRIN_PREFUSE on TOP: 169.32,107.65 173.76,107.65 174.27,107.14 174.27,102.57 173.51,101.81 168.94,101.81 168.3,102.44 168.3,106.63
VPWRIN_PREFUSE on BOTTOM: 165.38,107.65 172.49,107.65 173.89,106.25 173.89,102.21 173.48,101.81 165.38,101.81 164.49,102.7 164.49,106.76
VRTC_OUT on TOP: 141.35,135.84 141.99,135.84 142.11,135.72 142.11,133.18 141.61,132.67 140.84,132.67 140.21,133.3 140.21,134.7
VRTC_OUT on BOTTOM: 91.69,101.47 91.69,104.77 106.25,119.33 109.81,119.33 113.03,122.55 119.89,122.55 122.05,124.71 122.05,137.37 126.36,141.69 138.43,141.69 141.73,138.38 141.73,134.19 141.48,133.94 140.76,133.94 139.83,134.87 139.83,136.48 138.94,137.37 135,137.37 134.37,136.73 126.24,136.73 125.48,135.97 125.48,121.92 122.05,118.49 115.32,118.49 112.6,115.78 106.43,115.78 99.95,109.3 99.95,101.55 96.31,97.92 94.49,97.92 94.36,98.04 94.36,98.81
VSDMMC on BOTTOM: 113.66,123.7 113.66,126.75 112.14,128.27 112.14,131.7 111.76,132.08 109.98,132.08 109.73,131.83 109.73,128.14 111.89,125.98 111.89,123.7 112.27,123.32 113.28,123.32
VSDMMC on BOTTOM: 96.65,87.58 97.33,87.58 97.66,87.25 97.66,87.06 97.47,86.87 96.38,86.87 94.49,88.76 94.49,92.92 94.74,93.17 95.76,93.17 96.01,92.92 96.01,88.22
VSDMMC on BOTTOM: 86.89,149.18 87.86,149.18 88.06,148.98 88.06,146.44 88.8,145.7 92.76,145.7 93.32,146.26 93.32,149.48 93.62,149.79 94.97,149.79 95.12,149.64 95.12,144.02 95.63,143.51 97.92,143.51 100.15,141.27 100.15,139.58 98.83,138.26 95.8,138.26 90.98,143.08 88.7,143.08 86.61,145.17 86.61,148.9
VSDMMC on L4_SIG2: 84.58,109.56 85.72,109.56 86.61,108.67 86.61,103.84 95.76,94.7 95.76,91.65 94.36,90.25 92.96,90.25 90.8,92.41 90.8,94.95 90.02,95.74 85.83,95.74 82.68,98.89 82.68,107.65
VSDMMC on L10_SIG4: 92.94,92.77 95.38,92.77 95.66,92.49 95.66,89.67 95.35,89.36 92.96,89.36 92.71,89.62 92.71,92.54
VSDMMC on L10_SIG4: 109.73,132.72 111.25,132.72 111.89,132.08 111.89,130.81 111.51,130.43 110.49,130.43 109.47,131.44 109.47,132.46
VSMPS1_2 on TOP: 151.77,126.95 151.77,134.07 152.27,134.57 153.54,134.57 154.56,133.56 154.56,127.46 153.92,126.83 151.89,126.83
VSMPS1_2 on TOP: 113.16,134.6 116.31,134.6 116.71,134.19 116.71,130.76 116.15,130.21 114.83,130.21 113.03,132.01 113.03,134.47
VSMPS1_2 on BOTTOM: 151.64,133.81 152.4,134.57 154.18,134.57 154.69,134.07 154.69,126.95 154.31,126.57 152.02,126.57 151.64,126.95
VSMPS1_2 on L8_GND3: 153.04,125.56 152.78,125.3 147.49,125.3 146.69,126.11 146.69,128.27 145.67,129.29 144.35,129.29 142.24,131.4 138.43,131.4 130.18,123.14 111.38,123.14 111.12,123.4 111.12,133.94 112.39,135.21 129.54,135.21 137.41,143.08 149.48,143.08 153.04,139.53
VSMPS1_SW on TOP: 145.03,128.61 145.03,130.13 147.7,132.8 147.7,134.19 147.83,134.32 150.88,134.32 151.13,134.07 151.13,132.03 149.61,130.51 149.1,130.51 147.96,129.37 147.96,129.11 146.49,127.65 144.71,127.65 144.65,127.72 144.65,128.25 144.65,128.26 144.65,128.31 144.76,128.41 144.84,128.41
VSMPS2_SW on TOP: 145.03,127.21 146.69,127.21 148.34,128.86 148.34,129.11 148.59,129.37 150.88,129.37 151.26,128.99 151.26,126.07 151,125.81 145.16,125.81 144.7,126.28 144.7,126.87
VSMPS3 on TOP: 151.89,124.92 154.94,124.92 155.45,124.41 155.45,119.72 155.19,119.46 151.77,119.46 151.38,119.84 151.38,124.41
VSMPS3_SW on TOP: 150.88,124.92 150.37,125.43 145.92,125.43 145.29,124.8 145.29,124.03 145.92,123.4 147.57,123.4 149.1,121.87 150.5,121.87 150.88,122.26
VSMPS4_5 on TOP: 120.4,130.92 121.13,131.65 121.13,134.47 121.36,134.7 124,134.7 124.31,134.4 124.31,132.16 126.59,129.88 130.3,129.88 130.43,129.75 130.43,129.62 130.56,129.49 130.56,127.43 130.31,127.19 126.09,127.19 125.09,126.19 125.09,122.38 126.36,121.11 130.3,121.11 130.81,120.6 130.81,119.21 130.43,118.83 129.54,118.83 128.02,117.3 121.79,117.3 120.4,118.7
VSMPS4_5 on BOTTOM: 127.25,130 130.3,130 130.56,129.75 130.56,127.31 130.26,127.01 127.74,127.01 127.13,127.63 127.13,129.88
VSMPS4_5 on BOTTOM: 127.25,121.09 130.3,121.09 130.56,120.83 130.56,119.06 130.3,118.8 127.51,118.8 127.13,119.18 127.13,120.96
VSMPS4_SW on TOP: 127.43,126.8 130.47,126.8 131.63,127.97 133.22,127.97 133.6,127.59 133.6,126.18 133.22,125.8 132.06,125.8 130.79,124.53 127.4,124.53 127.19,124.74 127.19,126.57
VSMPS5_SW on TOP: 133.22,125.4 132.06,125.4 130.73,124.08 127.32,124.08 127.32,124.07 127.27,124.07 127.08,123.89 127.08,121.66 127.38,121.37 131.67,121.37 133.27,122.96 133.27,125.36
VSMPS6_SW on TOP: 133.6,116.42 133.57,116.4 133.57,115.43 133.99,115.02 136.91,115.02 138.03,116.14 138.03,120.37 138.03,120.62 137.82,120.83 137.67,120.68 137.67,119.94 136.81,119.08 134.11,119.08 133.6,118.56
VSMPS7 on TOP: 127.06,136.13 129.96,136.13 130.51,135.58 130.51,133.91 130.35,133.74 126.88,133.74 126.67,133.96 126.67,135.74
VSMPS7 on TOP: 105.79,134.7 107.52,134.7 107.65,134.57 107.65,131.7 107.34,131.4 105.92,131.4 105.54,131.78 105.54,134.45
VSMPS7 on BOTTOM: 127.13,134.07 127.13,135.84 127.51,136.23 130.18,136.23 130.68,135.72 130.68,134.19 130.35,133.86 127.33,133.86
VSMPS7 on L7_PWR2: 130.81,138.51 130.81,133.81 127.64,130.64 116.08,130.64 114.68,129.24 114.68,126.7 114.17,126.19 105.79,126.19 103.38,128.61 103.38,138.26 105.16,140.04 129.29,140.04
VSMPS7_SW on TOP: 127.47,132.59 130.3,132.59 130.3,132.54 133.99,128.86 134.9,128.86 134.87,128.84 136.22,128.84 136.33,128.73 136.33,128.22 136.23,128.13 136.11,128.13 135.98,128.26 135.72,128.26 135.67,128.21 135.59,128.13 134.24,128.13 134.04,128.34 132.22,128.34 130.18,130.38 127.25,130.38 127.12,130.51 127.12,132.24
VSMPS8_SW on TOP: 142.49,120.1 143,119.59 144.78,119.59 146.69,117.68 146.69,115.65 146.3,115.27 143.13,115.27 142.75,115.65 142.75,118.06 141.99,118.83 141.99,119.97 142.11,120.1
VSMPS9 on TOP: 138.81,113.62 141.1,113.62 142.09,112.63 142.09,111.05 141.61,110.57 138.56,110.57 138.18,110.95 138.18,112.98
VSMPS9 on BOTTOM: 139.34,125.7 139.57,125.93 140.72,125.93 140.97,125.68 140.97,124.41 140.84,124.29 138.18,124.29 137.92,124.03 137.92,123.14 136.27,123.14 136.14,123.27 136.14,125.3 136.54,125.7
VSMPS9 on L4_SIG2: 143.09,125.17 143.09,112.22 141.2,110.34 139.01,110.34 138.32,111.02 138.32,114.14 138.35,114.17 138.35,118.04 137.34,119.05 137.34,126.01 138.43,127.11 141.15,127.11
VSMPS9 on L10_SIG4: 137.67,126.32 141.22,126.32 141.61,125.94 141.61,124.41 141.35,124.16 137.67,124.16 137.54,124.29 137.54,126.19
VSMPS9_SW on TOP: 139.32,119.97 139.45,119.97 139.53,119.88 139.53,119.34 140.55,118.32 141.86,118.32 142.11,118.06 142.11,115.52 141.73,115.14 138.68,115.14 138.43,115.4 138.43,118.83 139.19,119.59 139.19,119.84
VUSB_FTDI on TOP: 178.62,16.85 178.97,17.2 179.78,17.2 180.14,16.84 180.14,15.88 179.91,15.65 175.01,15.65 174.75,15.9 174.75,16.59 175.01,16.85
VUSB_FTDI on TOP: 163.12,92.08 165.66,92.08 166.04,91.7 166.04,90.81 165.4,90.17 163.25,90.17 162.86,90.56 162.86,91.83
VUSB_FTDI on L8_GND3: 178.05,57.97 178.05,89.03 174.29,92.79 164.97,92.79 164.06,91.88 164.06,90.61 164.74,89.92 169.49,89.92 173.48,85.93 173.48,61.68 170.94,59.14 170.97,59.14 168.66,56.82 168.66,19.51 172.54,15.63 176.12,15.63 179.2,18.7 179.2,56.82
VUSB_JTAG on TOP: 182.12,16.9 182.3,16.72 183.15,16.72 183.36,16.51 183.36,15.49 183.01,15.14 181.27,15.14 180.64,15.77 180.64,17.93 180.88,18.17 181.89,18.17 182.12,17.94
VUSB_VBUS1 on BOTTOM: 25.27,13.34 25.27,10.29 25.53,10.03 29.21,10.03 29.59,10.41 29.59,13.08 28.83,13.84 25.78,13.84
VUSB_VBUS1 on BOTTOM: 33.02,6.35 33.99,6.35 35.13,7.49 37.82,7.49 38.28,7.04 38.28,2.21 37.46,1.4 33.15,1.4 32.51,2.03 32.51,5.84
VUSB_VBUS1 on L10_SIG4: 29.66,20.24 43.42,20.24 44.49,19.17 44.49,4.28 42.32,2.11 31.35,2.11 25.35,8.11 25.35,15.93
VUSB_VBUS2 on TOP: 8.94,34.24 8.13,35.05 8.13,40 7.21,40.92 6.73,40.92 6.73,41.36 7.11,41.74 8.38,41.74 8.64,41.48 8.64,40.98 9.02,40.59 10.46,40.59 11.56,39.5 16.72,39.5 17.78,38.44 19.56,38.44 19.81,38.69 19.81,40.59 20.07,40.85 24.4,40.85 26.09,39.17 26.09,37.92 22.41,34.24
VUSB_VBUS2 on BOTTOM: 3.43,39.96 9.78,39.96 10.03,39.71 10.03,37.67 9.78,37.42 8.51,37.42 7.24,38.69 5.84,38.69 4.95,39.58 3.43,39.58
N11220684 on TOP: 108.8,15.81 109.9,15.81 110.27,15.44 110.27,13.58 110.38,13.47 110.89,13.47 110.98,13.56 110.98,16.6 110.76,16.81 108.97,16.81 108.77,16.61 108.77,15.84
N12225158 on L3_SIG1: 26.54,100.54 28.53,100.54 31.58,97.49 33.27,97.49 33.91,96.86 33.91,96.22 33.27,95.59 24.54,95.59 24.21,95.92 24.21,98.2
N16839102 on BOTTOM: 188.75,74.93 188.98,74.71 188.98,72.34 186.82,70.19 185.93,70.19 185.93,72.12 184.53,73.52 184.53,74.75 184.71,74.93
N17594977 on L3_SIG1: 27.2,83.16 34.11,83.16 35.64,81.64 35.64,78.47 34.92,77.75 24.92,77.75 24.21,78.47 24.21,80.17
N17596823 on L3_SIG1: 26.03,58.76 32.29,58.76 35.64,55.41 35.64,53.88 35.26,53.5 34.37,53.5 33.6,54.26 24.59,54.26 24.21,54.64 24.21,56.93
N19923823 on BOTTOM: 110.01,92.48 110.95,92.48 111.12,92.31 111.12,91.6 110.85,91.32 110.13,91.32 109.86,91.6 109.86,92.33
N19923823 on L4_SIG2: 107.21,86.16 109.5,86.16 110.11,86.77 110.11,93.17 110.36,93.43 111.25,93.43 111.48,93.2 111.48,85.63 110.19,84.33 107.11,84.33 106.71,84.74 106.71,85.65
N19923823 on L10_SIG4: 109.92,91.33 109.92,93.11 110.17,93.36 110.68,93.36 110.81,93.24 110.81,91.46 110.55,91.2 110.05,91.2
N19923824 on L4_SIG2: 107.34,86.42 108.86,86.42 109.65,87.2 109.65,92.74 109.22,93.17 108.58,93.17 107.98,92.56 107.98,87.36 107.75,87.13 107.44,87.13 107.21,86.9 107.21,86.54
N19923824 on L10_SIG4: 108.39,91.08 108.39,92.85 108.65,93.11 109.16,93.11 109.28,92.98 109.28,91.2 109.03,90.95 108.52,90.95
N19923831 on BOTTOM: 118.67,77.8 118.67,76.94 118.44,76.71 117.98,76.71 117.73,76.97 117.73,77.85 117.86,77.98 118.49,77.98
N19923831 on L5_GND2: 106.63,77.86 119.13,77.86 119.43,77.55 119.43,77.12 119.2,76.89 114.1,76.89 113.59,76.38 111.61,76.38 111.1,76.89 106.6,76.89 106.38,77.12 106.38,77.6
N19923831 on L10_SIG4: 118.11,78.44 119.38,78.44 119.76,78.06 119.76,77.45 119.28,76.97 118.44,76.97 117.73,77.68 117.73,78.06
N19923833 on L4_SIG2: 106.4,86.47 106.91,86.47 107.29,86.85 107.29,87.05 107.59,87.36 107.62,87.36 107.62,92.61 107.06,93.17 106.55,93.17 106.3,92.92 106.3,89.24 105.61,88.55 105.61,87.51 106.3,86.82 106.3,86.57
N19923833 on L10_SIG4: 106.17,91.01 106.17,92.79 106.43,93.05 106.93,93.05 107.06,92.92 107.06,91.14 106.81,90.89 106.3,90.89
N19923834 on BOTTOM: 114.68,73.66 115.32,73.66 115.44,73.53 115.44,72.52 115.19,72.26 114.55,72.26 114.3,72.52 114.3,73.28
N19923834 on L7_PWR2: 107.21,77.7 108.08,77.7 108.74,77.04 113.39,77.04 115.09,75.34 115.09,74.05 114.78,73.74 114.33,73.74 111.99,76.08 107.98,76.08 107.04,77.02 107.04,77.53
N19923834 on L10_SIG4: 114.15,74.99 115.09,74.99 115.39,74.68 115.39,72.47 115.19,72.26 114.43,72.26 113.94,72.75 113.94,74.78
N19923844 on L4_SIG2: 106.05,86.57 106.05,86.67 105.54,87.18 105.54,91.78 104.39,92.92 103.89,92.92 103.61,92.64 103.61,86.26 103.89,85.98 105.46,85.98
N19923844 on L10_SIG4: 103.76,92.54 104.14,92.92 104.52,92.92 104.9,92.54 104.9,91.27 104.52,90.89 104.27,90.89 103.76,91.39
N19923846 on L3_SIG1: 102.87,76.66 102.87,71.07 103.63,70.31 103.63,69.68 103.38,69.42 102.49,69.42 102.11,69.8 102.11,75.65 101.09,76.66 101.09,76.92 101.35,77.17 102.36,77.17
N19923850 on L10_SIG4: 88.8,84.38 90.53,84.38 91.03,83.88 91.03,83.32 90.98,83.27 89.15,83.27 88.65,83.77 88.65,84.23
N19923853 on L10_SIG4: 103.12,76.54 103.12,70.06 101.85,68.79 100.97,68.79 99.19,70.57 99.19,75.87 100.49,77.17 102.49,77.17
N20127658 on BOTTOM: 81.28,86.87 82.17,86.87 82.42,86.61 82.42,85.17 82.25,84.99 81.2,84.99 81.1,85.09 81.1,86.69
N20127658 on L9_SIG3: 84.96,80.52 91.31,80.52 91.82,81.03 91.82,82.17 87.25,86.74 82.93,86.74 82.42,86.23 82.42,83.06
N20127658 on L10_SIG4: 82.17,86.87 83.26,86.87 83.72,86.41 83.72,85.7 82.98,84.96 82.04,84.96 81.79,85.22 81.79,86.49
N20127658 on L10_SIG4: 88.17,83.14 90.17,83.14 90.68,82.63 90.68,82.61 90.07,82 89.65,82 89.66,81.99 88.65,81.99 88.01,82.63 88.01,82.98
N20128389 on BOTTOM: 95.76,83.06 96.01,83.06 96.14,83.19 96.14,83.44 95.25,84.33 92.84,84.33 92.33,84.84 92.33,86.11 94.23,88.01 94.23,95.38 95.5,96.65 95.5,97.28 95.25,97.54 91.82,97.54 91.57,97.28 91.57,93.09 92.71,91.95 92.71,88.14 91.44,86.87 91.44,83.82 91.95,83.31 95.5,83.31
N20287584 on TOP: 159.38,123.91 159.13,124.15 159.13,125.56 159.51,125.94 159.51,134.07 159.64,134.19 160.66,134.19 161.67,133.18 161.67,129.11 161.42,128.86 161.42,124.09 161.24,123.91
N20619479 on BOTTOM: 70.74,113.24 70.74,114 70.87,114.13 72.9,114.13 73.15,114.38 73.91,114.38 74.04,114.25 74.04,113.11 73.91,112.98 73.28,112.98 73.15,113.11 70.87,113.11
N20664562 on BOTTOM: 155.02,107.01 155.02,107.25 154.67,107.6 154.67,108.49 153.47,109.7 153.47,112.62 152.83,113.25 151.43,113.25 151.05,112.87 151.05,109.95 152.83,108.17 153.85,108.17 155.01,107.01
N20665027 on BOTTOM: 159.05,112.87 159.05,110.35 155.99,107.28 155.63,107.28 155.63,107.37 155.91,107.65 155.91,108.69 155.63,108.97 155.63,112.87 156.13,113.38 158.55,113.38
N21552786 on BOTTOM: 157.99,56.52 157.99,54.48 158.12,54.36 161.04,54.36 161.16,54.48 161.16,54.86 160.78,55.24 159,55.24 158.75,55.5 158.75,56.52
N21605448 on TOP: 16,40 16.26,40.26 16.26,46.74 15.75,47.24 13.97,47.24 13.34,46.61 13.34,43.43 12.45,42.55 12.45,40.51 12.95,40
N21685968 on BOTTOM: 118.75,82.38 119.76,82.38 120.14,82 120.14,80.6 119.81,80.26 119.51,80.26 119,80.77 118.57,80.77 118.36,80.98 118.36,82
N21685968 on L7_PWR2: 106.55,83.14 118.24,83.14 118.62,82.76 118.62,82 118.36,81.74 106.55,81.74 106.3,82 106.3,82.89
N21685968 on L10_SIG4: 116.71,81.62 118.11,81.62 118.36,81.36 118.36,80.98 118.62,80.73 119.51,80.73 119.76,80.98 119.76,82.63 119.51,82.89 116.71,82.89 116.46,82.63 116.46,81.87
N22641301 on BOTTOM: 35.81,96.52 38.23,96.52 38.35,96.39 38.35,94.36 38.1,94.11 35.81,94.11 35.64,94.28 35.64,96.34
N22641309 on BOTTOM: 36.2,93.09 38.1,93.09 38.23,92.96 38.23,92.33 37.97,92.08 37.97,91.06 37.72,90.8 36.96,90.8 34.42,93.34 34.42,96.27 34.67,96.52 35.18,96.52 35.31,96.39 35.31,93.98
N22641383 on BOTTOM: 114.05,125.22 114.05,127.64 114.17,127.76 116.2,127.76 116.46,127.51 116.46,125.22 116.28,125.04 114.22,125.04
N22641391 on BOTTOM: 117.47,125.73 117.47,127.51 117.6,127.64 118.24,127.64 118.49,127.38 119.51,127.38 119.76,127.13 119.76,124.21 118.49,122.94 114.43,122.94 114.05,123.32 114.05,124.59 114.17,124.71 116.46,124.71

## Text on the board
BOTTOM: PN#: 3M0001 | LAYER 12 SECONDARY SIDE | 12
Ref Des/Silkscreen Bottom: A1 | A | 2 | 1 | 7 | 8 | 12 | 9 | 14 | 4 | B1 | 5 | B2 | A2 | A17 | B17 | A18 | B18 | 59 | 60 | 3 | 29 | 24 | 23 | 30 | +
TOP: LAYER 1 - PRIMARY SIDE | 1 | 12
Ref Des/Silkscreen Top: 1 | 5 | 2 | 3 | 4 | 29 | 30 | 24 | 23 | 7 | 8 | A2 | A1 | B2 | B1 | A18 | A17 | B17 | B18 | 5.0VDC | 4.0A | GND | PRU2 ETH1 | PRU2 ETH0 | PRU1ETH1 | PRU1ETH0 | Gb Ethernet0 | USB1 | Gb Ethernet1 | VDDS_DDR1 | HDMI | Profibus | VDD | VDD_MPU | VDD_DSPEVE | Expansion Connector | CAN | RS-485 | Warm | Hard | Reset | Power On | 8A Slow Blow | 125VAC, 125VDC | VMAIN | CAMERA | INDUSTRIAL LED0 | INDUSTRIAL LED1 | INDUSTRIAL LED2 | INDUSTRIAL LED3 | STATUS LED1 | STATUS LED0 | JTAG | USB JTAG | Industrial I/O | OPN# | PROJ# | S/N# | PROC053 | REV A | PCIE | SD/MMC1 | For evaluation only; not | FCC approved for resale
PAGE_OUTLINE: TI
DIMENSION: SILKSCREEN TOP | 1 | 2
DEVICE_TYPE_TOP: A1 | A | 1 | 2 | 7 | 8 | 12 | 9 | 14 | 4 | B1 | 5 | B2 | A2 | A17 | B17 | A18 | B18 | 59 | 60 | 3 | 29 | 24 | 23 | 30 | ASSEMBLY BOTTOM | +
DEVICE_TYPE_BOTTOM: 1 | 5 | 2 | 3 | 4 | 29 | 30 | 24 | 23 | 7 | 8 | A2 | A1 | B2 | B1 | A18 | A17 | B17 | B18 | * | ASSEMBLY TOP | Assembly Notes: | 1. These assemblies are ESD sensitive. | ESD precautians shall be observed. | 2. These assemblies must be clean and | free from flux and all contaminants. Use | of 'no clean flux' is not acceptable. | 3. These assemblies must comply with | workmanship standard IPC-A-610 Class 2, | unless otherwise specified. | 4. Each finished board will receive a | serial number sticker during final | testing. | 5. Each finished board will receive a | MAC Address sticker during final | 6. Install header shunt M1 (on J49) and | M2 (on J50) during final testing. | +
User.7: FABRICATION DRAWING | 1
User.8: LAYER 2 - GROUND LAYER 1 | 2 | 12
User.9: LAYER 3 - SIGNAL LAYER 1 | 3 | 12
User.10: LAYER 4 - SIGNAL LAYER 2 | 4 | 12
User.11: LAYER 5 - GROUND LAYER 2 | 5 | 12
User.12: SOLDER MASK BOTTOM | 2
User.13: SOLDER MASK TOP | 1 | 2
User.14: SOLDER PASTE BOTTOM | 2
User.15: SOLDER PASTE TOP | 1 | 2
User.16: SILKSCREEN BOTTOM | 2
User.18: LAYER 6 - POWER LAYER 1 | 6 | 12
User.19: LAYER 7 -POWER LAYER 2 | 7 | 12
User.20: ACTIVE AREA CENTER | LCD CONNECTOR LOCATION | LCD AND TS TOP VIEW
User.23: LAYER 8 - GROUND LAYER 3 | 8 | 12
User.24: LAYER 9 - SIGNAL LAYER 3 | 9 | 12
User.25: LAYER 10 - SIGNAL LAYER 4 | 10 | 12
User.26: LAYER 11 - GROUND LAYER 4 | 11 | 12
User.27: SELECTIVE PLATING TOP | 1
User.28: BOARD NAME: | BOARD NO: PROC053 | CUSTOMER NAME: | AM574X_INDUSTRIAL_EVM | TEXAS INSTRUMENTS | REV: A | DESCRIPTION: | DATE: 03/13/2018 | SH | OF
User.29: OF | SH | DATE:03/13/2018 | DESCRIPTION: | TEXAS INSTRUMENTS | REV:A | AM574X_INDUSTRIAL_EVM | BOARD NAME: | CUSTOMER NAME: | BOARD NO:PR0C053
User.30: L9_SIG3 | L1_TOP | L3_SIG1 | L4_SIG2 | L10_SIG4 | L12_BOTTOM | LAYERS | in mils | TRACE | WIDTH | 4.3 | 4.5 | 6.8 | +/-10% | TARGET | SINGLE-ENDED | Ohms | 50 | 4.2 | - | 60 | 5.9 | EDGE-COUPLED DIFFERENTIAL | SPACE | 7.7 | 6.1 | 90 | 3.25 | 4.25 | 3.9 | 8.75 | 8.1 | 5.75 | 100
User.33: IMPEDANCE REQUIREMENT :- THIS DESIGN MAY NOT CONTAIN ALL THE FEATURES | NOTE : | LISTED IN THE ABOVE TABLE | 10. DESIGN HAS INTENTIONAL SHORTS AT U95 COMPONENT AS SHOWN IN IPC356 NETLIST. | 11. ALL DRILLS TO HAVE POSITIONAL TOLERANCE OF +/- 3 MIL. | CLASS 2 AND WORKMANSHIP SHALL CONFORM TO | IPC-A-600, CLASS 2. CURRENT REVISIONS. | 2. THE PWB SHALL BE FABRICATED TO IPC-6012, | 9. ALL VIAS TO HAVE SOLDERMASK. | 3. BOARD MATERIAL SHALL BE 180 Tg/350 Td ISOLA FR-370 HR | OR EQUIVALENT, RoHS COMPLIANT AND LEAD FREE | ASSEMBLY CAPABLE.  BOARD MATERIAL SHALL | MEET OR EXCEED IPC-4101B. COLOR: NATURAL. | 5. MINIMUM COPPER WALL THICKNESS OF PLATED-THRU | HOLES TO BE .001 INCH, WITH A MINIMUM | ANNULAR RING OF .002 INCH. | 4. BOARD MATERIAL & CONSTRUCTION TO BE UL94V0 CERTIFIED | AND MARKED ON TOP SIDE OF FINISHED BOARD. | FAB NOTES: | 6. OVERALL BOARD THICKNESS TO BE 0.0625" +/- 10% | AND APPLIES AFTER ALL LAMINATION AND PLATING | 1. ALL DIMENSIONS ARE IN INCHES, UNLESS | OTHERWISE NOTED. | SUPPLIED IPC-D-356 NETLIST. | PROCESSES, MEASURED FROM COPPER TO COPPER. | 8. BOARD MUST BE ELECTRICALLY TESTED USING | 7. MAX. WARP & TWIST TO BE .0075 INCHES PER INCH. | 2. APPLY LPI SOLDERMASK OVER BARE COPPER (SMOBC), | COLOR: BLACK SOLDERMASK SHALL | CONFORM TO IPC-SM-840, CLASS H. CURRENT REV. | 3. SOLDERMASK ARTWORK HAS ZERO (0) OVERSIZED PADS. | FABRICATION VENDOR IS ALLOWED TO ADJUST THE COMPONENT | SOLDERMASK PADS TO MEET THEIR TOOLING REQUIREMENTS. | 4. APPLY LPI SILKSCREEN OR EQUIVALENT PER THE ARTWORK. | 200uIN OF NICKEL. KNOOP HARDNESS 130-200. | COLOR: WHITE. | 5. A) ALL CORE AND PREPREG THICKNESSES ARE UP TO FAB SHOP TO SELECT. | B) EXTERNAL LAYER CU THICKNESSES ARE FINISHED THICKNESS AFTER PLATING. | PROCESS NOTES: | 1. A) PLATE CIRCUITARY ON OUTER LAYERS TO 2-5uIN OF GOLD OVER
User.36: FIGURE | SIZE | 5.0 | 8.0 | DRILL CHART: L2_GND1 to L3_SIG1 | ALL UNITS ARE IN MILS | TOLERANCE | +0.0/-5.0 | +0.0/-8.0 | PLATED | QTY | 620 | 613
User.37: FIGURE | SIZE | 5.0 | 8.0 | DRILL CHART: TOP to L2_GND1 | ALL UNITS ARE IN MILS | TOLERANCE | +0.0/-5.0 | +0.0/-8.0 | PLATED | QTY | 620 | 613
User.40: FIGURE | SIZE | 8.0 | 10.0 | 28.0 | 28.35 | 30.0 | 33.0 | 35.04 | 40.0 | 40.16 | 43.0 | 45.0 | 45.28 | 50.0 | 67.0 | 68.9 | 90.0 | 120.0 | 140.0 | 33.46 | 59.0 | 92.52 | 125.98 | 138.0 | DRILL CHART: TOP to BOTTOM | ALL UNITS ARE IN MILS | TOLERANCE | +0.0/-8.0 | +0.0/-10.0 | +3.0/-3.0 | +2.0/-2.0 | PLATED | NON-PLATED | QTY | 1201 | 1510 | 9 | 36 | 2 | 60 | 52 | 44 | 54 | 4 | 24 | 6 | 12 | 1
